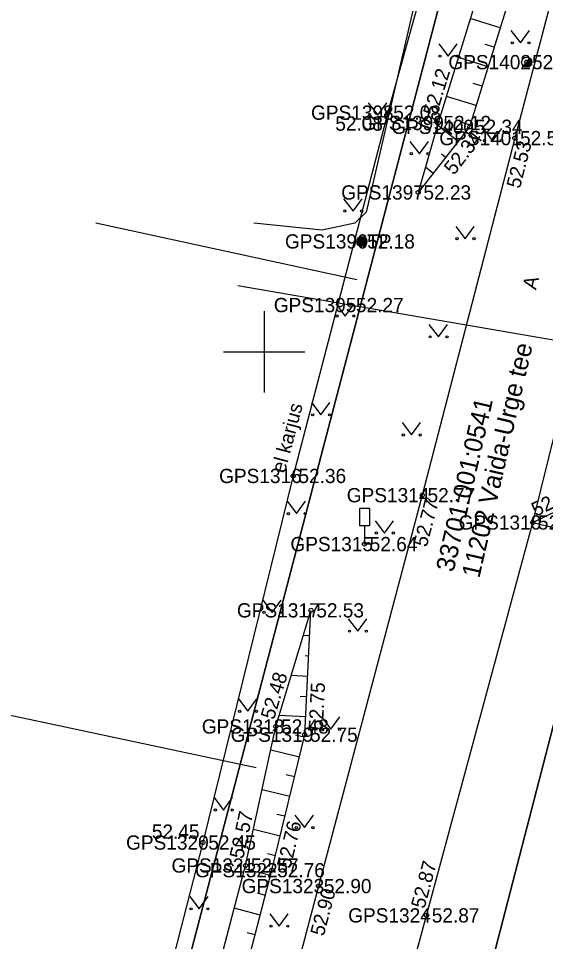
# Model space of a CAD drawing. Extents: x 551623 to 559850, y 6561220 to 6567135.
# Drawn here: x 555137.92 to 555163.83, y 6565121.03 to 6565166.39 of the extents above; entities that cross this region are included whole.
import ezdxf

# ---------------------------------------------------------------- set-up
doc = ezdxf.new("R2010")
doc.units = 0
for name, color, linetype in [('AED', 7, 'Continuous'), ('DTRASS', 7, 'Continuous'), ('HALJASTUS', 7, 'Continuous'), ('KORGUS-EH2000', 7, 'Continuous'), ('KPKAABEL', 7, 'Continuous'), ('KPOHULIIN', 7, 'Continuous'), ('LIIKLUS', 7, 'Continuous'), ('MOOTKORG-EH2000', 7, 'Continuous'), ('MOOTMPUNKT', 7, 'Continuous'), ('MOOTNR', 7, 'Continuous'), ('MOOTPIIR', 7, 'Continuous'), ('PIIR', 7, 'Continuous'), ('POST', 7, 'Continuous'), ('RELJEEF', 7, 'Continuous'), ('TEE', 7, 'Continuous'), ('VORK', 7, 'Continuous')]:
    doc.layers.add(name, color=color, linetype=linetype)

msp = doc.modelspace()

# ---------------------------------------------------------------- linework, layer by layer
at = {"layer": 'AED'}
msp.add_lwpolyline([(555179.37, 6565300.078), (555180.242, 6565299.846), (555180.75, 6565290.874), (555180.137, 6565280.616), (555178.982, 6565264.788), (555177.984, 6565255.288), (555177.306, 6565249.05), (555173.486, 6565227.422), (555169.733, 6565212.423), (555163.779, 6565189.534), (555156.086, 6565161.758), (555151.428, 6565143.905), (555146.995, 6565125.891), (555142.273, 6565107.514), (555136.767, 6565086.759), (555131.214, 6565064.984), (555128.386, 6565056.617), (555127.142, 6565056.522)], dxfattribs=at)
at = {"layer": 'DTRASS'}
for p, q in [((555154.563, 6565153.548), (555141.731, 6565156.319)), ((555149.601, 6565129.561), (555127.945, 6565134.156))]:
    msp.add_line(p, q, dxfattribs=at)
at = {"layer": 'HALJASTUS'}
for p, q in [((555162.132, 6565165.796), (555162.596, 6565165.19)), ((555162.596, 6565165.19), (555163.041, 6565165.796)), ((555158.583, 6565165.141), (555159.046, 6565164.534)), ((555159.046, 6565164.534), (555159.492, 6565165.141)), ((555155.119, 6565162.234), (555155.583, 6565161.627)), ((555155.583, 6565161.627), (555156.028, 6565162.234)), ((555160.768, 6565160.986), (555161.231, 6565160.379)), ((555161.231, 6565160.379), (555161.677, 6565160.986)), ((555157.169, 6565160.345), (555157.632, 6565159.738)), ((555157.632, 6565159.738), (555158.078, 6565160.345)), ((555153.905, 6565157.527), (555154.369, 6565156.92)), ((555154.369, 6565156.92), (555154.814, 6565157.527)), ((555159.422, 6565156.171), (555159.885, 6565155.564)), ((555159.885, 6565155.564), (555160.331, 6565156.171)), ((555153.519, 6565152.37), (555153.983, 6565151.764)), ((555153.983, 6565151.764), (555154.428, 6565152.37)), ((555158.1, 6565151.349), (555158.563, 6565150.742)), ((555158.563, 6565150.742), (555159.009, 6565151.349)), ((555152.323, 6565147.515), (555152.787, 6565146.909)), ((555152.787, 6565146.909), (555153.232, 6565147.515)), ((555156.778, 6565146.526), (555157.241, 6565145.92)), ((555157.241, 6565145.92), (555157.687, 6565146.526)), ((555151.127, 6565142.66), (555151.591, 6565142.054)), ((555151.591, 6565142.054), (555152.036, 6565142.66)), ((555155.456, 6565141.704), (555155.919, 6565141.098)), ((555155.919, 6565141.098), (555156.365, 6565141.704)), ((555149.932, 6565137.806), (555150.395, 6565137.199)), ((555150.395, 6565137.199), (555150.841, 6565137.806)), ((555154.134, 6565136.882), (555154.598, 6565136.276)), ((555154.598, 6565136.276), (555155.043, 6565136.882)), ((555148.736, 6565132.951), (555149.199, 6565132.344)), ((555149.199, 6565132.344), (555149.645, 6565132.951)), ((555152.812, 6565132.06), (555153.276, 6565131.454)), ((555153.276, 6565131.454), (555153.721, 6565132.06)), ((555147.54, 6565128.096), (555148.003, 6565127.489)), ((555148.003, 6565127.489), (555148.449, 6565128.096)), ((555151.516, 6565127.231), (555151.979, 6565126.625)), ((555151.979, 6565126.625), (555152.425, 6565127.231)), ((555146.344, 6565123.241), (555146.807, 6565122.634)), ((555146.807, 6565122.634), (555147.253, 6565123.241)), ((555150.276, 6565122.387), (555150.74, 6565121.781)), ((555150.74, 6565121.781), (555151.185, 6565122.387))]:
    msp.add_line(p, q, dxfattribs=at)
for centre in [(555162.195, 6565165.19), (555163.024, 6565165.19), (555158.645, 6565164.534), (555159.474, 6565164.534), (555155.182, 6565161.627), (555156.01, 6565161.627), (555160.83, 6565160.379), (555161.659, 6565160.379), (555157.231, 6565159.738), (555158.06, 6565159.738), (555153.968, 6565156.92), (555154.796, 6565156.92), (555159.484, 6565155.564), (555160.313, 6565155.564), (555153.582, 6565151.764), (555154.41, 6565151.764), (555158.162, 6565150.742), (555158.991, 6565150.742), (555152.386, 6565146.909), (555153.214, 6565146.909), (555156.84, 6565145.92), (555157.669, 6565145.92), (555151.19, 6565142.054), (555152.019, 6565142.054), (555155.518, 6565141.098), (555156.347, 6565141.098), (555149.994, 6565137.199), (555150.823, 6565137.199), (555154.197, 6565136.276), (555155.025, 6565136.276), (555148.798, 6565132.344), (555149.627, 6565132.344), (555152.875, 6565131.454), (555153.703, 6565131.454), (555147.602, 6565127.489), (555148.431, 6565127.489), (555151.578, 6565126.625), (555152.407, 6565126.625), (555146.406, 6565122.634), (555147.235, 6565122.634), (555150.339, 6565121.781), (555151.167, 6565121.781)]:
    msp.add_circle(centre, 0.055, dxfattribs=at)
at = {"layer": 'KORGUS-EH2000'}
for centre in [(555156.086, 6565161.758), (555158.553, 6565161.251), (555160.102, 6565161.063), (555162.32, 6565160.507), (555154.255, 6565152.303), (555151.428, 6565143.905), (555157.772, 6565142.96), (555163.2, 6565141.618), (555150.576, 6565131.594), (555151.998, 6565131.189), (555146.995, 6565125.891), (555149.086, 6565124.763), (555150.38, 6565124.533), (555152.674, 6565123.751), (555157.981, 6565122.311)]:
    msp.add_circle(centre, 0.1, dxfattribs=at)
at = {"layer": 'KPKAABEL'}
msp.add_lwpolyline([(555166.139, 6565359.889), (555169.783, 6565348.422), (555171.572, 6565337.25), (555172.523, 6565325.522), (555172.476, 6565313.268), (555172.511, 6565302.969), (555172.901, 6565290.135), (555172.887, 6565279.431), (555172.817, 6565266.938), (555172.536, 6565254.014), (555171.281, 6565241.464), (555170.488, 6565231.192), (555168.866, 6565217.1), (555167.048, 6565204.461), (555164.351, 6565191.399), (555161.107, 6565179.306), (555157.628, 6565168.142), (555155.008, 6565156.873), (555154.465, 6565156.331), (555152.85, 6565155.986), (555149.5, 6565156.323)], dxfattribs=at)
at = {"layer": 'KPOHULIIN'}
msp.add_lwpolyline([(555148.701, 6565153.258), (555226.644, 6565139.855), (555319.309, 6565121.586)], dxfattribs=at)
at = {"layer": 'LIIKLUS'}
for p, q in [((555154.681, 6565142.306), (555154.681, 6565141.457)), ((555155.181, 6565142.306), (555154.681, 6565142.306)), ((555155.181, 6565142.306), (555155.181, 6565141.457)), ((555155.181, 6565141.457), (555154.681, 6565141.457)), ((555154.931, 6565141.457), (555154.931, 6565140.556)), ((555155.181, 6565140.556), (555154.931, 6565140.556))]:
    msp.add_line(p, q, dxfattribs=at)
at = {"layer": 'MOOTMPUNKT'}
for centre in [(555162.907, 6565164.24), (555156.086, 6565161.758), (555158.553, 6565161.251), (555160.102, 6565161.063), (555162.32, 6565160.507), (555157.57, 6565157.837), (555154.806, 6565155.43), (555154.255, 6565152.303), (555151.428, 6565143.905), (555157.772, 6565142.96), (555163.2, 6565141.618), (555154.931, 6565140.556), (555152.304, 6565137.301), (555150.576, 6565131.594), (555151.998, 6565131.189), (555146.995, 6565125.891), (555149.086, 6565124.763), (555150.38, 6565124.533), (555152.674, 6565123.751), (555157.981, 6565122.311)]:
    msp.add_circle(centre, 0.1, dxfattribs=at)
at = {"layer": 'MOOTPIIR'}
for points in [[(555159.402, 6565375.941), (555168.348, 6565355.185), (555172.166, 6565344.528), (555174.522, 6565333.321), (555178.521, 6565317.128), (555179.431, 6565307.904), (555179.588, 6565301.089), (555179.37, 6565300.078), (555180.137, 6565280.616), (555177.984, 6565255.288), (555173.486, 6565227.422), (555163.779, 6565189.534), (555156.086, 6565161.758), (555151.428, 6565143.905), (555146.995, 6565125.891), (555142.273, 6565107.514), (555136.767, 6565086.759)], [(555147.465, 6565082.979), (555153.125, 6565104.459), (555157.981, 6565122.311), (555163.2, 6565141.618), (555175.303, 6565138.726), (555190.232, 6565137.368), (555210.946, 6565134.177), (555222.4, 6565133.017), (555236.459, 6565117.362), (555247.686, 6565098.015), (555255.514, 6565098.946), (555277.06, 6565106.584), (555291.997, 6565107.634)]]:
    msp.add_lwpolyline(points, dxfattribs=at)
at = {"layer": 'PIIR'}
for points in [[(555171.91, 6565394.64), (555191.35, 6565341.19), (555195.08, 6565294.61), (555195.28, 6565271.63), (555191.64, 6565237.48), (555173.84, 6565168.77), (555173.21, 6565166.35), (555172.58, 6565163.93), (555140.74, 6565041.04), (555133.32, 6565012.53), (555119.68, 6564972.95), (555107.79, 6564965.53), (555093.78, 6564958.98), (555080.97, 6564954.71), (555007.97, 6564939.78), (554928.66, 6564923.99)], [(554924.73, 6564941.05), (555076.32, 6564971.61), (555087.28, 6564975.26), (555098.22, 6564980.37), (555106.03, 6564987.06), (555108.27, 6564991.27), (555117.14, 6565008.97), (555172.7, 6565220.76), (555176.93, 6565240.09), (555179.22, 6565254.85), (555180.41, 6565269.99), (555180.8, 6565287.7), (555180.26, 6565306.43), (555178.11, 6565321.18), (555176.49, 6565331.05), (555172.72, 6565345.23), (555166.64, 6565360.5)]]:
    msp.add_lwpolyline(points, dxfattribs=at)
for points in [[(554962.55, 6565234.93), (555180.26, 6565306.43), (555180.8, 6565287.7), (555180.41, 6565269.99), (555179.22, 6565254.85), (555176.93, 6565240.09), (555172.7, 6565220.76), (555117.14, 6565008.97), (555108.27, 6564991.27)], [(555172.58, 6565163.93), (555173.21, 6565166.35), (555225.89, 6565157.13), (555231.12, 6565150.64), (555239.11, 6565139), (555273.15, 6565087.34), (555275.41, 6565088.83), (555288.85, 6565092.31), (555289.83, 6565088.53), (555295.15, 6565083.63), (555324.46, 6565074.96), (555339.51, 6565058.58), (555337.29, 6565046.66), (555323.9, 6565035.68), (555298.08, 6565033.06), (555286.82, 6565022.41), (555284.62, 6565010.72), (555273.43, 6565013.07), (555140.74, 6565041.04)]]:
    msp.add_lwpolyline(points, close=True, dxfattribs=at)
at = {"layer": 'POST'}
msp.add_line((555162.73, 6565164.063), (555163.084, 6565164.417), dxfattribs=at)
for centre, radius in [((555162.907, 6565164.24), 0.25), ((555154.806, 6565155.43), 0.25), ((555154.806, 6565155.43), 0.225), ((555154.806, 6565155.43), 0.2), ((555154.806, 6565155.43), 0.175), ((555154.806, 6565155.43), 0.15), ((555154.806, 6565155.43), 0.125), ((555154.806, 6565155.43), 0.1), ((555154.806, 6565155.43), 0.075), ((555154.806, 6565155.43), 0.05), ((555154.806, 6565155.43), 0.025)]:
    msp.add_circle(centre, radius, dxfattribs=at)
for radius, start, end in [(0.225, 224.8541, 45.0356), (0.2, 224.8427, 45.047), (0.175, 224.8281, 45.0616), (0.15, 224.8087, 45.081), (0.125, 224.7814, 45.1083), (0.1, 224.7406, 45.1491), (0.075, 224.6725, 45.2172), (0.05, 224.5363, 45.3534), (0.025, 224.1278, 45.7619)]:
    msp.add_arc((555162.907, 6565164.24), radius, start, end, dxfattribs=at)
at = {"layer": 'RELJEEF'}
for p, q in [((555161.609, 6565165.925), (555160.135, 6565166.382)), ((555161.313, 6565164.97), (555160.871, 6565165.107)), ((555161.016, 6565164.015), (555159.546, 6565164.471)), ((555160.72, 6565163.06), (555160.28, 6565163.196)), ((555160.424, 6565162.104), (555158.957, 6565162.559)), ((555159.54, 6565160.347), (555158.523, 6565161.146)), ((555160.128, 6565161.149), (555159.689, 6565161.286)), ((555158.923, 6565159.561), (555158.713, 6565159.725)), ((555158.305, 6565158.774), (555157.926, 6565159.072)), ((555157.688, 6565157.987), (555157.67, 6565158.002)), ((555152.292, 6565137.054), (555152.273, 6565137.055)), ((555152.242, 6565136.056), (555151.932, 6565136.071)), ((555152.192, 6565135.057), (555152.024, 6565135.065)), ((555152.142, 6565134.058), (555151.334, 6565134.099)), ((555152.092, 6565133.059), (555151.775, 6565133.075)), ((555152.042, 6565132.061), (555150.737, 6565132.126)), ((555151.968, 6565131.065), (555151.539, 6565131.17)), ((555151.732, 6565130.094), (555150.323, 6565130.436)), ((555151.496, 6565129.122), (555151.08, 6565129.223)), ((555151.26, 6565128.15), (555149.897, 6565128.481)), ((555151.024, 6565127.179), (555150.622, 6565127.276)), ((555150.787, 6565126.207), (555149.471, 6565126.527)), ((555150.551, 6565125.235), (555150.163, 6565125.329)), ((555150.311, 6565124.264), (555149.042, 6565124.593)), ((555150.06, 6565123.296), (555149.678, 6565123.395)), ((555149.809, 6565122.328), (555148.532, 6565122.659)), ((555149.558, 6565121.36), (555149.174, 6565121.46))]:
    msp.add_line(p, q, dxfattribs=at)
for points in [[(555184.566, 6565294.895), (555185.953, 6565280.072), (555185.143, 6565263.746), (555184.046, 6565254.819), (555183.226, 6565249.112), (555179.005, 6565228.311), (555174.467, 6565210.622), (555168.444, 6565187.982), (555160.102, 6565161.063), (555157.57, 6565157.837)], [(555184.566, 6565294.895), (555182.784, 6565279.965), (555183.347, 6565264.524), (555181.678, 6565255.565), (555181.412, 6565249.474), (555177.118, 6565228.691), (555172.906, 6565211.208), (555166.985, 6565188.606), (555158.553, 6565161.251), (555157.57, 6565157.837)], [(555119.659, 6565010.325), (555123.707, 6565025.312), (555129.009, 6565045.265), (555134.764, 6565064.612), (555140.243, 6565085.297), (555145.723, 6565106.564), (555150.38, 6565124.533), (555151.998, 6565131.189), (555152.304, 6565137.301)], [(555119.659, 6565010.325), (555122.574, 6565025.466), (555127.459, 6565046.429), (555133.335, 6565064.856), (555138.641, 6565085.815), (555144.363, 6565106.834), (555149.086, 6565124.763), (555150.576, 6565131.594), (555152.304, 6565137.301)]]:
    msp.add_lwpolyline(points, dxfattribs=at)
at = {"layer": 'TEE'}
for points in [[(555165.93, 6565378.047), (555174.733, 6565357.312), (555178.536, 6565346.409), (555181.58, 6565335.07), (555184.177, 6565320.727), (555185.301, 6565309.018), (555186.111, 6565294.522), (555186.299, 6565280.132), (555185.431, 6565263.333), (555184.399, 6565254.7), (555183.594, 6565248.995), (555179.697, 6565227.862), (555175.388, 6565210.507), (555169.433, 6565187.479), (555162.32, 6565160.507), (555157.772, 6565142.96), (555152.674, 6565123.751), (555148.003, 6565106.069), (555142.307, 6565084.705)], [(555114.997, 6564980.207), (555119.473, 6564986.791), (555121.429, 6564990.442), (555124.132, 6564996.667), (555128.448, 6565009.121), (555131.982, 6565022.769), (555137.234, 6565043.213), (555142.087, 6565062.036), (555147.465, 6565082.979), (555153.125, 6565104.459), (555157.981, 6565122.311), (555163.2, 6565141.618), (555168.3, 6565162.209), (555168.744, 6565163.563), (555174.483, 6565185.521), (555180.709, 6565208.971), (555185.087, 6565226.838), (555186.799, 6565233.51), (555187.911, 6565235.651)], [(555163.2, 6565141.618), (555168.594, 6565144.246), (555172.571, 6565146.598), (555178.227, 6565145.611), (555191.847, 6565141.953), (555195.778, 6565139.63), (555200.739, 6565133.541)]]:
    msp.add_lwpolyline(points, dxfattribs=at)
at = {"layer": 'VORK'}
for p, q in [((555150, 6565152), (555150, 6565148)), ((555148, 6565150), (555152, 6565150))]:
    msp.add_line(p, q, dxfattribs=at)

# ---------------------------------------------------------------- texts
at = {"layer": 'AED'}
msp.add_text('el karjus', height=0.7, rotation=75.2255, dxfattribs=at).set_placement((555151.021, 6565144.012))
at = {"layer": 'KORGUS-EH2000'}
for s, rotation, p in [(' 52.12', 72.8698, (555158.386, 6565161.303)), (' 52.34', 51.8761, (555159.167, 6565158.447)), (' 52.53', 75.4707, (555162.507, 6565157.744)), (' 52.73', 25.9799, (555163.124, 6565141.775)), (' 52.77', 75.1347, (555157.924, 6565140.126)), (' 52.48', 73.1511, (555150.408, 6565131.644)), (' 52.75', 87.1331, (555152.872, 6565131.145)), (' 52.57', 77.7006, (555148.915, 6565124.8)), (' 52.76', 76.3395, (555151.231, 6565124.326)), (' 52.87', 74.8738, (555157.813, 6565122.357)), (' 52.90', 75.2031, (555152.862, 6565121.006))]:
    msp.add_text(s, height=0.7, rotation=rotation, dxfattribs=at).set_placement(p)
for s, p in [(' 52.08', (555153.238, 6565160.871)), (' 52.27', (555154.255, 6565151.953)), (' 52.36', (555151.428, 6565143.555)), (' 52.45', (555144.221, 6565126.078))]:
    msp.add_text(s, height=0.7, dxfattribs=at).set_placement(p)
at = {"layer": 'MOOTKORG-EH2000'}
for s, p in [(' 52.33', (555162.907, 6565163.89)), (' 52.08', (555156.086, 6565161.408)), (' 52.12', (555158.553, 6565160.901)), (' 52.34', (555160.102, 6565160.713)), (' 52.53', (555162.32, 6565160.157)), (' 52.23', (555157.57, 6565157.487)), (' 52.18', (555154.806, 6565155.08)), (' 52.27', (555154.255, 6565151.953)), (' 52.36', (555151.428, 6565143.555)), (' 52.77', (555157.772, 6565142.61)), (' 52.73', (555163.2, 6565141.268)), (' 52.64', (555154.931, 6565140.207)), (' 52.53', (555152.304, 6565136.951)), (' 52.48', (555150.576, 6565131.244)), (' 52.75', (555151.998, 6565130.839)), (' 52.45', (555146.995, 6565125.541)), (' 52.57', (555149.086, 6565124.413)), (' 52.76', (555150.38, 6565124.183)), (' 52.90', (555152.674, 6565123.401)), (' 52.87', (555157.981, 6565121.961))]:
    msp.add_text(s, height=0.7, dxfattribs=at).set_placement(p)
at = {"layer": 'MOOTNR'}
for s, p in [('GPS1402 ', (555159.057, 6565163.89)), ('GPS1398 ', (555152.306, 6565161.408)), ('GPS1399 ', (555154.774, 6565160.901)), ('GPS1400 ', (555156.252, 6565160.713)), ('GPS1401 ', (555158.61, 6565160.157)), ('GPS1397 ', (555153.79, 6565157.487)), ('GPS1396 ', (555151.026, 6565155.08)), ('GPS1395 ', (555150.475, 6565151.953)), ('GPS1316 ', (555147.788, 6565143.555)), ('GPS1314 ', (555154.062, 6565142.61)), ('GPS1310 ', (555159.561, 6565141.268)), ('GPS1315 ', (555151.292, 6565140.207)), ('GPS1317 ', (555148.665, 6565136.951)), ('GPS1318 ', (555146.936, 6565131.244)), ('GPS1319 ', (555148.358, 6565130.839)), ('GPS1320 ', (555143.215, 6565125.541)), ('GPS1321 ', (555145.447, 6565124.413)), ('GPS1322 ', (555146.601, 6565124.183)), ('GPS1323 ', (555148.894, 6565123.401)), ('GPS1324 ', (555154.132, 6565121.961))]:
    msp.add_text(s, height=0.7, dxfattribs=at).set_placement(p)
at = {"layer": 'PIIR'}
for s, p in [('11202 Vaida-Urge tee', (555160.577, 6565138.851)), ('33701:001:0541', (555159.31, 6565139.141))]:
    msp.add_text(s, height=0.9, rotation=77.1047, dxfattribs=at).set_placement(p)
at = {"layer": 'POST'}
msp.add_text(' TP', height=0.7, dxfattribs=at).set_placement((555154.806, 6565155.08))
at = {"layer": 'TEE'}
msp.add_text('A', height=0.7, rotation=75.6331, dxfattribs=at).set_placement((555163.361, 6565153.021))

doc.saveas('drawing.dxf')
